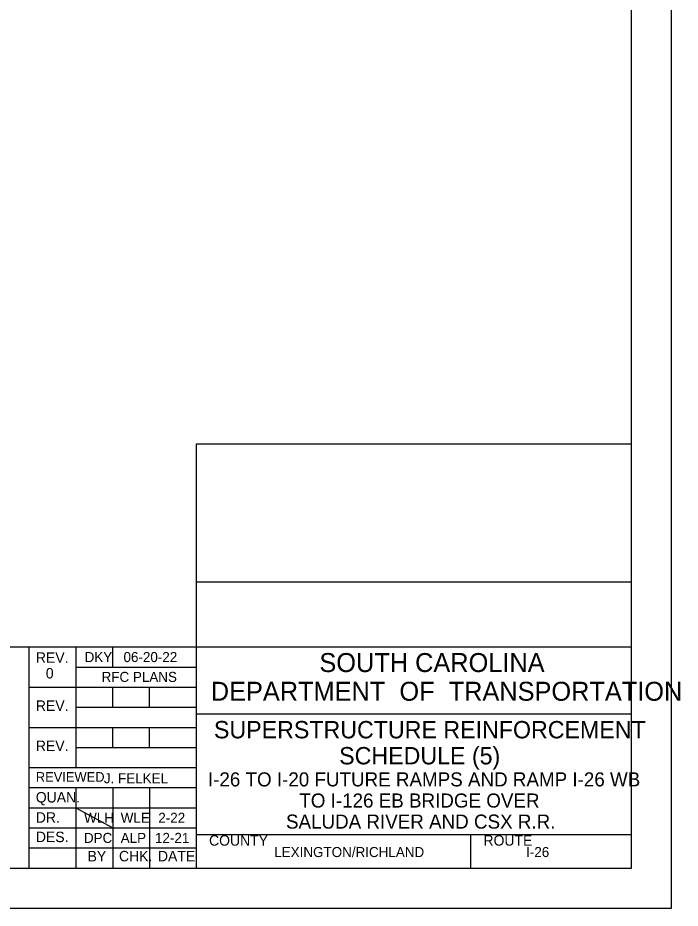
# Model space of a CAD drawing. Extents: x -133.1 to -97, y -1.7 to 20.5.
# Drawn here: x -105.28 to -97.03, y -1.69 to 9.39 of the extents above; entities that cross this region are included whole.
import ezdxf

# ---------------------------------------------------------------- set-up
doc = ezdxf.new("R2010")
doc.units = 0
for name, color, linetype in [('BR_BORDER LINES', 7, 'Continuous'), ('BR_TEXT', 7, 'Continuous'), ('Level 31', 7, 'Continuous')]:
    doc.layers.add(name, color=color, linetype=linetype)

msp = doc.modelspace()

# ---------------------------------------------------------------- linework, layer by layer
at = {"layer": 'BR_BORDER LINES'}
for p, q in [((-97.642, -1.191), (-97.642, 19.809)), ((-103.058, -1.191), (-103.058, 4.086)), ((-103.058, 4.086), (-97.642, 4.086)), ((-103.058, 2.371), (-97.642, 2.371)), ((-110.507, 1.559), (-105.142, 1.559)), ((-105.142, -1.191), (-105.142, 1.559)), ((-105.142, 1.559), (-97.642, 1.559)), ((-104.559, 1.559), (-104.559, 0.059)), ((-104.1, 1.309), (-104.1, 1.559)), ((-104.559, 1.309), (-103.058, 1.309)), ((-105.142, 1.059), (-103.058, 1.059)), ((-104.1, 0.809), (-104.1, 1.059)), ((-103.642, 0.809), (-103.642, 1.059)), ((-104.559, 0.809), (-103.058, 0.809)), ((-103.058, 0.726), (-103.058, 0.726)), ((-103.058, 0.726), (-97.641, 0.726)), ((-105.142, 0.559), (-103.058, 0.559)), ((-104.1, 0.309), (-104.1, 0.559)), ((-103.642, 0.309), (-103.642, 0.559)), ((-104.559, 0.309), (-103.058, 0.309)), ((-105.142, 0.059), (-103.058, 0.059)), ((-105.142, -0.191), (-103.058, -0.191)), ((-104.559, -0.191), (-104.559, -1.191)), ((-104.1, -0.191), (-104.1, -1.191)), ((-103.642, -0.191), (-103.642, -1.191)), ((-105.142, -0.441), (-103.058, -0.441)), ((-105.142, -0.691), (-103.058, -0.691)), ((-103.058, -0.774), (-97.642, -0.774)), ((-102.961, -0.774), (-97.642, -0.774)), ((-99.642, -1.191), (-99.642, -0.774)), ((-105.142, -0.941), (-103.058, -0.941)), ((-131.308, -1.191), (-97.642, -1.191))]:
    msp.add_line(p, q, dxfattribs=at)
at = {"layer": 'Level 31'}
for p, q in [((-100.35, 0.285), (-100.35, 0.285)), ((-104.559, -0.441), (-104.1, -0.691))]:
    msp.add_line(p, q, dxfattribs=at)
msp.add_lwpolyline([(-133.141, -1.691), (-97.141, -1.691), (-97.141, 20.309), (-133.141, 20.309)], close=True, dxfattribs=at)

# ---------------------------------------------------------------- texts
at = {"layer": 'BR_TEXT'}
for s, height, p in [('REV.', 0.13, (-105.057, 1.362)), ('DKY', 0.125, (-104.45, 1.371)), ('06-20-22', 0.125, (-103.966, 1.371)), ('SOUTH CAROLINA', 0.23587, (-101.527, 1.247)), ('0', 0.13, (-104.933, 1.167)), ('RFC PLANS', 0.125, (-104.239, 1.124)), ('DEPARTMENT  OF  TRANSPORTATION', 0.23587, (-102.879, 0.89)), ('REV.', 0.13, (-105.057, 0.764)), ('SUPERSTRUCTURE REINFORCEMENT', 0.216, (-102.84, 0.422)), ('REV.', 0.13, (-105.057, 0.264)), ('SCHEDULE (5)', 0.216, (-101.281, 0.098)), ('REVIEWED', 0.12, (-105.058, -0.118)), ('I-26 TO I-20 FUTURE RAMPS AND RAMP I-26 WB', 0.175, (-102.915, -0.176)), ('J. FELKEL', 0.125, (-104.211, -0.137)), ('QUAN.', 0.13, (-105.058, -0.376)), ('TO I-126 EB BRIDGE OVER', 0.175, (-101.777, -0.439)), ('DR.', 0.13, (-105.058, -0.627)), ('WLH', 0.125, (-104.457, -0.629)), ('WLE', 0.125, (-104.001, -0.629)), ('2-22', 0.125, (-103.533, -0.629)), ('SALUDA RIVER AND CSX R.R.', 0.175, (-101.943, -0.701)), ('DES.', 0.13, (-105.057, -0.869)), ('DPC', 0.125, (-104.459, -0.879)), ('ALP', 0.125, (-104.001, -0.879)), ('12-21', 0.125, (-103.574, -0.879)), ('COUNTY', 0.13, (-102.901, -0.913)), ('ROUTE', 0.13, (-99.484, -0.913)), ('BY', 0.13, (-104.413, -1.109)), ('CHK.', 0.13, (-104.022, -1.108)), ('DATE', 0.13, (-103.537, -1.108)), ('LEXINGTON/RICHLAND', 0.12499, (-102.089, -1.055)), ('I-26', 0.125, (-98.953, -1.055))]:
    msp.add_text(s, height=height, dxfattribs=at).set_placement(p)

doc.saveas('drawing.dxf')
